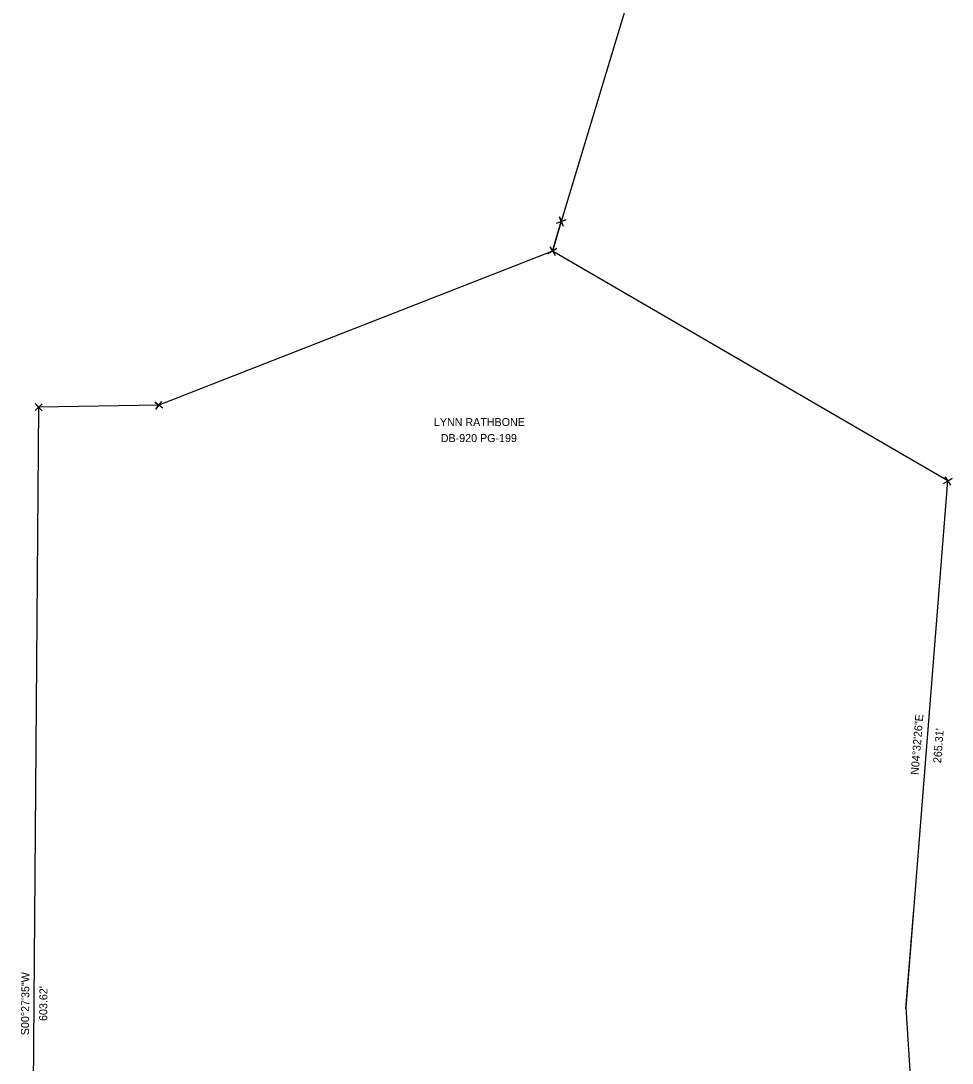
# Model space of a CAD drawing. Extents: x 831731 to 833706, y 722402 to 726085.
# Drawn here: x 831900 to 832368, y 724515 to 725038 of the extents above; entities that cross this region are included whole.
import ezdxf

# ---------------------------------------------------------------- set-up
doc = ezdxf.new("R2010")
doc.units = 0
for name, color, linetype in [('Exist Property Corner CELL', 7, 'Continuous'), ('Exist Property Line', 7, 'Continuous'), ('Exist Property Text', 7, 'Continuous'), ('Scratch_Level_0', 7, 'Continuous')]:
    doc.layers.add(name, color=color, linetype=linetype)

msp = doc.modelspace()

# ---------------------------------------------------------------- linework, layer by layer
at = {"layer": 'Exist Property Corner CELL'}
for p, q in [((832171.86, 724937.64), (832171.86, 724937.64)), ((832167.44, 724922.8), (832167.44, 724922.8)), ((831909.37, 724844.45), (831909.37, 724844.45)), ((831969.71, 724845.38), (831969.71, 724845.38)), ((832366.01, 724807.33), (832366.01, 724807.33))]:
    msp.add_line(p, q, dxfattribs=at)
for points in [[(832169.52, 724936.77), (832174.21, 724938.51), (832171.86, 724937.64), (832170.99, 724939.98), (832172.73, 724935.29)], [(832165.28, 724921.54), (832169.6, 724924.06), (832167.44, 724922.8), (832166.18, 724924.96), (832168.7, 724920.64)], [(831911.08, 724842.62), (831907.66, 724846.27), (831909.37, 724844.45), (831907.55, 724842.74), (831911.19, 724846.16)], [(831971.66, 724843.82), (831967.76, 724846.94), (831969.71, 724845.38), (831968.15, 724843.43), (831971.27, 724847.33)], [(832363.87, 724806.02), (832368.14, 724808.63), (832366.01, 724807.33), (832364.7, 724809.46), (832367.31, 724805.19)]]:
    msp.add_lwpolyline(points, dxfattribs=at)
at = {"layer": 'Exist Property Line'}
for p, q in [((832261.37, 725234.8), (832171.86, 724937.64)), ((832171.86, 724937.64), (832167.44, 724922.8)), ((832167.44, 724922.8), (831969.71, 724845.38)), ((832366.01, 724807.33), (832167.44, 724922.8)), ((831909.37, 724844.45), (831904.52, 724240.84)), ((831969.71, 724845.38), (831909.37, 724844.45)), ((832345, 724542.84), (832366.01, 724807.33)), ((832358.2, 724340.06), (832345, 724542.84))]:
    msp.add_line(p, q, dxfattribs=at)
at = {"layer": 'Scratch_Level_0'}
for p, q in [((832167.44, 724922.8), (832171.86, 724937.64)), ((832344.87, 724542.34), (832348.85, 724592.18))]:
    msp.add_line(p, q, dxfattribs=at)

# ---------------------------------------------------------------- texts
at = {"layer": 'Exist Property Text'}
for s, p in [('LYNN RATHBONE', (832107.86, 724834.92)), ('DB-920 PG-199', (832111.32, 724826.88))]:
    msp.add_text(s, height=4.02, dxfattribs=at).set_placement(p)
for s, rotation, p in [('N04°32\'26"E', 85.4593, (832351.27, 724659.6)), ("265.31'", 85.4593, (832362.57, 724665.51)), ('S00°27\'35"W', 89.5402, (831904.5, 724528.93)), ("603.62'", 89.5402, (831913.65, 724536.1))]:
    msp.add_text(s, height=4.02, rotation=rotation, dxfattribs=at).set_placement(p)

doc.saveas('drawing.dxf')
